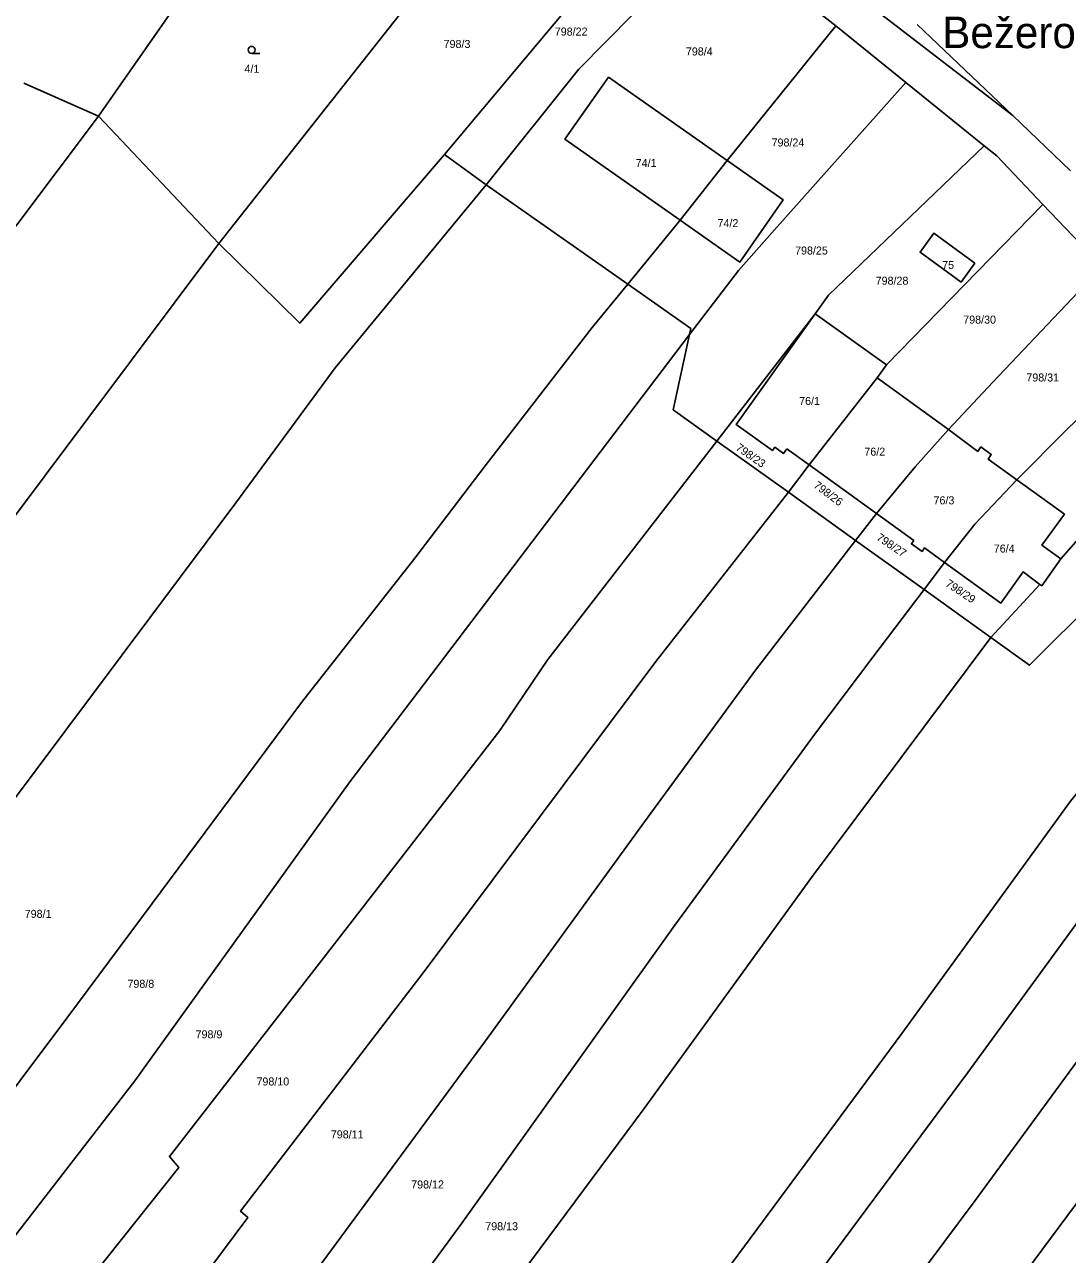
# Model space of a CAD drawing. Extents: x -7476540 to -746055, y -11317203 to -1129777.
# Drawn here: x -747915.8 to -747694.4, y -1131418.4 to -1131157.3 of the extents above; entities that cross this region are included whole.
import ezdxf

# ---------------------------------------------------------------- set-up
doc = ezdxf.new("R2010")
doc.units = 0
for name, color, linetype in [('Hranice parcel', 7, 'Continuous'), ('Parcelní čísla', 7, 'Continuous'), ('Pop  PČ popisy', 7, 'Continuous'), ('Značky kultur', 7, 'Continuous')]:
    doc.layers.add(name, color=color, linetype=linetype)

msp = doc.modelspace()

# ---------------------------------------------------------------- linework, layer by layer
at = {"layer": 'Hranice parcel'}
for p, q in [((-747826.65, -1131184.92), (-747779.57, -1131128.72)), ((-747743.52, -1131157.59), (-747769.22, -1131137.45)), ((-747874.56, -1131203.77), (-747836.24, -1131155.33)), ((-747766.58, -1131186.19), (-747743.52, -1131157.59)), ((-747743.52, -1131157.59), (-747728.7, -1131169.57)), ((-747705.95, -1131176.64), (-747726.24, -1131157.28)), ((-747728.7, -1131169.57), (-747712.03, -1131183.04)), ((-747915.95, -1131169.75), (-747900.11, -1131176.75)), ((-747900.11, -1131176.75), (-747874.56, -1131203.77)), ((-747693.71, -1131188.35), (-747705.95, -1131176.64)), ((-747817.77, -1131191.32), (-747826.65, -1131184.92)), ((-747776.59, -1131198.85), (-747766.58, -1131186.19)), ((-747787.74, -1131212.45), (-747817.77, -1131191.32)), ((-747732.77, -1131229.55), (-747699.59, -1131195.48)), ((-747699.59, -1131195.48), (-747686.96, -1131208.76)), ((-747787.74, -1131212.45), (-747776.59, -1131198.85)), ((-747774.35, -1131221.87), (-747787.74, -1131212.45)), ((-747747.94, -1131218.7), (-747768.78, -1131245.74)), ((-747732.77, -1131229.55), (-747747.94, -1131218.7)), ((-747774.62, -1131223.12), (-747774.35, -1131221.87)), ((-747778.06, -1131239.08), (-747774.62, -1131223.12)), ((-747734.74, -1131232.31), (-747732.77, -1131229.55)), ((-747749.21, -1131250.8), (-747734.74, -1131232.31)), ((-747719.59, -1131243.31), (-747734.74, -1131232.31)), ((-747768.78, -1131245.74), (-747778.06, -1131239.08)), ((-747713.41, -1131247.97), (-747719.59, -1131243.31)), ((-747753.62, -1131256.62), (-747768.78, -1131245.74)), ((-747753.92, -1131247.41), (-747749.21, -1131250.8)), ((-747753.62, -1131256.62), (-747749.21, -1131250.8)), ((-747749.21, -1131250.8), (-747734.88, -1131261.12)), ((-747739.39, -1131266.83), (-747753.62, -1131256.62)), ((-747739.39, -1131266.83), (-747734.88, -1131261.12)), ((-747734.88, -1131261.12), (-747726.94, -1131266.84)), ((-747724.81, -1131277.29), (-747739.39, -1131266.83)), ((-747724.81, -1131277.29), (-747720.46, -1131271.5)), ((-747710.63, -1131287.46), (-747700.19, -1131276.18)), ((-747710.63, -1131287.46), (-747724.81, -1131277.29))]:
    msp.add_line(p, q, dxfattribs=at)
for points in [[(-747866.49, -1131129.32), (-747883.09, -1131152.34), (-747900.11, -1131176.75)], [(-747764.01, -1131130.51), (-747750.16, -1131141.94), (-747739.59, -1131150.73), (-747705.95, -1131176.64)], [(-747769.22, -1131137.45), (-747798.15, -1131166.84), (-747817.77, -1131191.32)], [(-747776.59, -1131198.85), (-747801.07, -1131181.67), (-747791.81, -1131168.48), (-747766.58, -1131186.19)], [(-747774.62, -1131223.12), (-747764.24, -1131209.52), (-747756.55, -1131200.89), (-747728.7, -1131169.57)], [(-748086.2, -1131411.99), (-748063.76, -1131390.25), (-748037.84, -1131359.52), (-747984.99, -1131289.67), (-747934.84, -1131222.88), (-747900.11, -1131176.75)], [(-747874.56, -1131203.77), (-747857.38, -1131220.73), (-747826.65, -1131184.92)], [(-747747.94, -1131218.7), (-747745.11, -1131214.77), (-747712.03, -1131183.04)], [(-747712.03, -1131183.04), (-747709.37, -1131185.19), (-747699.59, -1131195.48)], [(-747776.59, -1131198.85), (-747763.95, -1131207.73), (-747754.69, -1131194.54), (-747766.58, -1131186.19)], [(-747817.77, -1131191.32), (-747849.87, -1131230.22), (-747870.95, -1131258.84), (-747919.45, -1131323.71), (-747970.67, -1131391.64), (-747999.11, -1131427.19), (-748029.39, -1131463.51), (-748052.97, -1131487.38)], [(-747714.02, -1131207.99), (-747722.72, -1131201.59), (-747725.64, -1131205.64), (-747716.93, -1131211.98), (-747714.02, -1131207.99)], [(-748069.53, -1131447.82), (-748039.5, -1131417.64), (-748010.54, -1131383.33), (-747969.15, -1131330.2), (-747939.35, -1131290.2), (-747874.56, -1131203.77)], [(-747719.59, -1131243.31), (-747710.17, -1131233.27), (-747686.96, -1131208.76)], [(-748039.41, -1131527.57), (-748021.11, -1131510.35), (-748001.42, -1131490.57), (-747960.37, -1131438.84), (-747946.8, -1131421.49), (-747906.82, -1131368.28), (-747888.73, -1131343.94), (-747857, -1131301.23), (-747832.91, -1131270.59), (-747818.02, -1131250.97), (-747795.27, -1131221.64), (-747787.74, -1131212.45)], [(-747747.94, -1131218.7), (-747764.72, -1131242.22), (-747757.01, -1131247.77), (-747756.49, -1131247.04), (-747754.62, -1131248.38), (-747753.92, -1131247.41)], [(-748030.59, -1131550.68), (-748006.8, -1131528.34), (-747986.12, -1131504.66), (-747956.18, -1131464.19), (-747938.32, -1131440.9), (-747892.39, -1131381.59), (-747846.71, -1131318.11), (-747774.62, -1131223.12)], [(-747705.1, -1131253.98), (-747694.48, -1131243.3), (-747684.57, -1131233.76), (-747673.07, -1131223.37)], [(-747695.74, -1131270.78), (-747683.08, -1131256.39), (-747661.79, -1131238.73)], [(-747734.88, -1131261.12), (-747726.72, -1131251.2), (-747719.59, -1131243.31)], [(-748020.54, -1131577.02), (-748001.95, -1131555.56), (-747973.86, -1131518.8), (-747960.03, -1131500.15), (-747932.73, -1131464.51), (-747901.57, -1131423.28), (-747883.06, -1131399.99), (-747885.07, -1131397.67), (-747846.34, -1131347.72), (-747814.92, -1131307.18), (-747804.7, -1131292.12), (-747768.78, -1131245.74)], [(-747705.1, -1131253.98), (-747711.22, -1131249.55), (-747710.52, -1131248.58), (-747712.71, -1131246.99), (-747713.41, -1131247.97)], [(-747720.46, -1131271.5), (-747714.03, -1131263.42), (-747705.1, -1131253.98)], [(-747695.74, -1131270.78), (-747699.76, -1131267.83), (-747695.01, -1131261.29), (-747705.1, -1131253.98)], [(-748006.35, -1131589.51), (-747976.31, -1131553.75), (-747942.87, -1131510.32), (-747895.09, -1131446.4), (-747868.39, -1131410.63), (-747869.95, -1131409.28), (-747831.18, -1131358.67), (-747781.73, -1131292.56), (-747753.62, -1131256.62)], [(-747991.94, -1131600.7), (-747981.03, -1131587.21), (-747950.23, -1131550.08), (-747903.91, -1131491.23), (-747862.5, -1131433.61), (-747817.95, -1131373.1), (-747784.2, -1131326.61), (-747760.62, -1131294.4), (-747739.39, -1131266.83)], [(-747726.94, -1131266.84), (-747727.47, -1131267.57), (-747725.23, -1131269.17), (-747724.71, -1131268.44), (-747720.46, -1131271.5)], [(-747700.19, -1131276.18), (-747699.8, -1131276.47), (-747695.74, -1131270.78)], [(-747720.46, -1131271.5), (-747708.48, -1131280.13), (-747703.77, -1131273.54), (-747700.19, -1131276.18)], [(-747972.95, -1131605.36), (-747952.16, -1131580.99), (-747925.8, -1131548.77), (-747894.55, -1131508.92), (-747869.95, -1131475.83), (-747822.94, -1131411.83), (-747777.73, -1131348.55), (-747747.86, -1131307.75), (-747735.67, -1131291.6), (-747724.81, -1131277.29)], [(-747669.82, -1131292.66), (-747687.96, -1131278.99), (-747702.43, -1131293.35), (-747710.63, -1131287.46)], [(-747953.56, -1131610.11), (-747936.63, -1131589.74), (-747927.22, -1131580.6), (-747917.02, -1131567.38), (-747880.11, -1131518.39), (-747857.18, -1131486.6), (-747811.82, -1131424.61), (-747784.23, -1131387.47), (-747748.68, -1131338.4), (-747710.63, -1131287.46)], [(-747915.42, -1131619.45), (-747873.23, -1131566.86), (-747843.82, -1131525.97), (-747806.53, -1131475.44), (-747778.43, -1131437.61), (-747729.49, -1131371.5), (-747693.71, -1131322.2), (-747669.82, -1131292.66)], [(-747895.76, -1131621.42), (-747861.58, -1131578.6), (-747835.67, -1131543.4), (-747806.42, -1131503.18), (-747795.07, -1131488.14), (-747755.24, -1131433.32), (-747715.49, -1131379.82), (-747681.87, -1131333.76), (-747656, -1131302.39)], [(-747879, -1131625.66), (-747851.66, -1131591.69), (-747829.65, -1131563.42), (-747808.64, -1131535.34), (-747757.65, -1131465.52), (-747713.97, -1131406.96), (-747691.09, -1131375.78), (-747664.28, -1131339.63), (-747646.2, -1131316.75), (-747642.09, -1131312.59)], [(-747860.06, -1131629.88), (-747832.75, -1131596.26), (-747816.97, -1131575.83), (-747776.82, -1131523.47), (-747762.78, -1131503.59), (-747734.31, -1131465.05), (-747710.2, -1131431.58), (-747690.98, -1131405.7), (-747669.96, -1131376.28), (-747627.04, -1131321.32)]]:
    msp.add_lwpolyline(points, dxfattribs=at)
at = {"layer": 'Značky kultur'}
msp.add_line((-747867.59, -1131163.43), (-747865.84, -1131163.43), dxfattribs=at)
msp.add_circle((-747867.59, -1131162.68), 0.75, dxfattribs=at)

# ---------------------------------------------------------------- texts
at = {"layer": 'Parcelní čísla'}
for s, p in [('798/22', (-747803.22, -1131159.64)), ('798/3', (-747826.83, -1131162.27)), ('798/4', (-747775.38, -1131163.86)), ('4/1', (-747869.11, -1131167.55)), ('798/24', (-747757.18, -1131183.19)), ('74/1', (-747786.04, -1131187.55)), ('74/2', (-747768.66, -1131200.32)), ('798/25', (-747752.19, -1131206.13)), ('75', (-747720.96, -1131209.21)), ('798/28', (-747735.08, -1131212.54)), ('798/30', (-747716.48, -1131220.8)), ('798/31', (-747703.08, -1131233.09)), ('76/1', (-747751.33, -1131238.08)), ('76/2', (-747737.48, -1131248.84)), ('76/3', (-747722.79, -1131259.17)), ('76/4', (-747710, -1131269.42)), ('798/1', (-747915.79, -1131346.98)), ('798/8', (-747893.97, -1131361.83)), ('798/9', (-747879.5, -1131372.56)), ('798/10', (-747866.57, -1131382.57)), ('798/11', (-747850.78, -1131393.81)), ('798/12', (-747833.72, -1131404.44)), ('798/13', (-747817.98, -1131413.31))]:
    msp.add_text(s, height=1.7, dxfattribs=at).set_placement(p)
for s, rotation, p in [('798/23', 325, (-747764.93, -1131247.5)), ('798/26', 323, (-747748.4, -1131255.45)), ('798/27', 326, (-747735.05, -1131266.6)), ('798/29', 326, (-747720.39, -1131276.39))]:
    msp.add_text(s, height=1.7, rotation=rotation, dxfattribs=at).set_placement(p)
at = {"layer": 'Pop  PČ popisy'}
msp.add_text('Bežerovice', height=6.7, dxfattribs=at).set_placement((-747720.95, -1131162.31))

doc.saveas('drawing.dxf')
